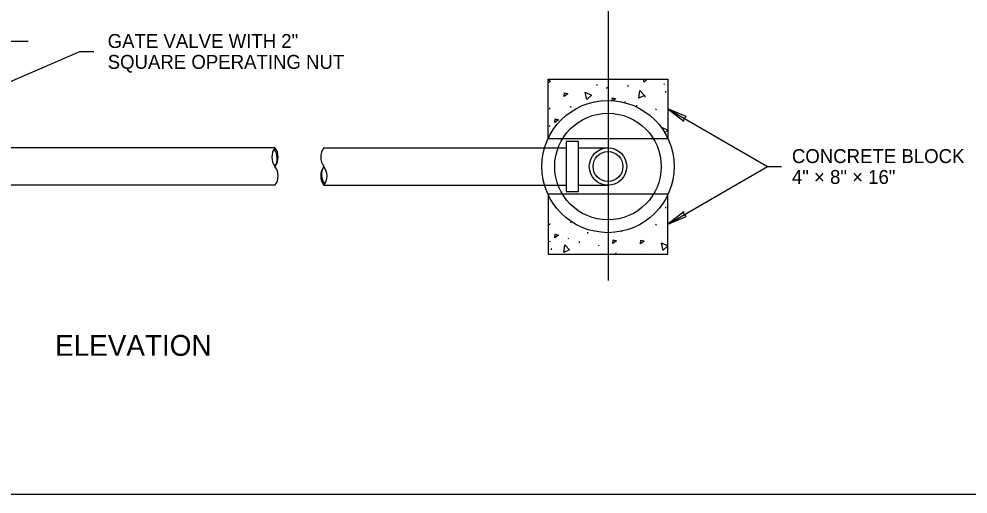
# Model space of a CAD drawing. Extents: x 99862 to 103151, y 99999 to 102075.
# Drawn here: x 100960 to 102052, y 99999 to 100546 of the extents above; entities that cross this region are included whole.
import ezdxf

# ---------------------------------------------------------------- set-up
doc = ezdxf.new("R2010")
doc.units = 0
for name, color, linetype in [('Level 1', 7, 'Continuous'), ('Level 13', 7, 'Continuous'), ('Level 15', 7, 'Continuous'), ('Level 17', 7, 'Continuous'), ('Level 19', 7, 'Continuous'), ('Level 20', 7, 'Continuous'), ('Level 6', 7, 'Continuous')]:
    doc.layers.add(name, color=color, linetype=linetype)

msp = doc.modelspace()

# ---------------------------------------------------------------- linework, layer by layer
at = {"layer": 'Level 1'}
msp.add_lwpolyline([(99862, 99999.5), (103151, 99999.5), (103151, 102075.5), (99862, 102075.5)], close=True, dxfattribs=at)
at = {"layer": 'Level 13'}
msp.add_line((100805, 100411.6), (101030.1, 100508.7), dxfattribs=at)
at = {"layer": 'Level 15'}
for p, q in [((101637.9, 101063.6), (101637.9, 100245)), ((100802.9, 100520.6), (100970.8, 100520.6)), ((101030.1, 100508.7), (101046.1, 100508.7)), ((101706.7, 100442.5), (101821.4, 100376.3)), ((101706.7, 100310), (101821.4, 100376.3)), ((101821.4, 100376.3), (101837.4, 100376.3))]:
    msp.add_line(p, q, dxfattribs=at)
for points in [[(101706.7, 100442.5), (101724.9, 100428.5), (101725.5, 100431.6), (101727.9, 100433.7)], [(101706.7, 100310), (101727.9, 100318.9), (101725.5, 100320.9), (101724.9, 100324)]]:
    msp.add_lwpolyline(points, close=True, dxfattribs=at)
at = {"layer": 'Level 17'}
for p, q in [((101706.7, 100408.1), (101568.9, 100408.1)), ((101706.7, 100344.5), (101568.9, 100344.5))]:
    msp.add_line(p, q, dxfattribs=at)
for points in [[(101568.9, 100408.1), (101568.9, 100476.9), (101706.7, 100476.9), (101706.7, 100408.1)], [(101568.9, 100344.5), (101568.9, 100275.6), (101706.7, 100275.6), (101706.7, 100344.5)]]:
    msp.add_lwpolyline(points, dxfattribs=at)
at = {"layer": 'Level 19'}
for p, q in [((101624.6, 100470.6), (101625.3, 100469.4)), ((101636.6, 100466.2), (101636.7, 100467.7)), ((101660.9, 100468.3), (101661.1, 100469.8)), ((101701.9, 100471.5), (101702.8, 100470.8)), ((101680.4, 100456.2), (101680.5, 100457.7)), ((101704.3, 100461.4), (101704.4, 100463)), ((101595.2, 100444.4), (101595.3, 100445.9)), ((101657.1, 100451), (101658, 100450.3)), ((101670.9, 100445.5), (101671, 100447)), ((101570.8, 100442.3), (101570.9, 100443.8)), ((101692.6, 100442.8), (101693.5, 100442.1)), ((101570.3, 100423.6), (101571.2, 100422.9)), ((101704.3, 100328.5), (101704.4, 100330)), ((101570.8, 100309.3), (101570.9, 100310.8)), ((101595.2, 100311.4), (101595.3, 100312.9)), ((101692.6, 100309.8), (101693.5, 100309.1)), ((101591.4, 100294), (101592.3, 100293.4)), ((101614.6, 100299.3), (101614.7, 100300.8)), ((101570.3, 100290.6), (101571.2, 100289.9)), ((101572.7, 100280.6), (101572.8, 100282.1)), ((101605.1, 100288.6), (101605.2, 100290.1)), ((101626.8, 100285.9), (101627.7, 100285.2)), ((101646.6, 100277.2), (101647.3, 100276)), ((101683, 100275.6), (101683.1, 100276.4))]:
    msp.add_line(p, q, dxfattribs=at)
for points in [[(101568.9, 100476.8), (101571.6, 100474), (101568.9, 100472.7)], [(101679.3, 100473.3), (101678.5, 100476.9)], [(101683, 100476.9), (101679.4, 100473.4)], [(101587.4, 100456.8), (101587.8, 100461.1), (101591.5, 100460), (101587.4, 100456.8)], [(101613.5, 100453.3), (101611.6, 100462), (101618.8, 100458.5), (101613.6, 100453.4)], [(101673.1, 100454.9), (101674.3, 100463.8), (101679.9, 100458.1), (101673.2, 100455)], [(101642.6, 100452.2), (101642.9, 100455.3), (101646.6, 100454.1), (101643.9, 100452.1)], [(101576.7, 100427), (101577.1, 100431.3), (101580.8, 100430.2), (101576.7, 100427)], [(101699.6, 100420.6), (101699.4, 100421.6), (101706.6, 100418.1), (101703.3, 100414.9)], [(101568.9, 100343.8), (101569.1, 100343.7)], [(101570.6, 100340.5), (101568.9, 100339.8)], [(101576.7, 100294.1), (101577.1, 100298.3), (101580.8, 100297.2), (101576.7, 100294.1)], [(101652.6, 100301.4), (101652.7, 100301.7)], [(101653.7, 100301.9), (101652.8, 100301.4)], [(101586.8, 100277.4), (101588.1, 100286.3), (101593.6, 100280.6), (101587, 100277.5)], [(101643.5, 100287.6), (101643.9, 100291.9), (101647.6, 100290.8), (101643.5, 100287.6)], [(101675.1, 100287.3), (101675.6, 100291.6), (101679.3, 100290.5), (101675.1, 100287.3)], [(101701.3, 100279.8), (101699.4, 100288.6), (101706.6, 100285.1), (101701.4, 100279.9)]]:
    msp.add_lwpolyline(points, dxfattribs=at)
at = {"layer": 'Level 6'}
for p, q in [((101254.6, 100397.8), (100832.7, 100397.8)), ((101310.9, 100397.8), (101564.9, 100397.8)), ((101564.8, 100397.8), (101589.7, 100397.8)), ((101604, 100397.8), (101637.7, 100397.8)), ((101254.6, 100354.8), (100832.7, 100354.8)), ((101310.9, 100354.8), (101564.9, 100354.8)), ((101564.8, 100354.8), (101589.7, 100354.8)), ((101604, 100354.8), (101637.7, 100354.8))]:
    msp.add_line(p, q, dxfattribs=at)
for points in [[(101604, 100347.6), (101604, 100405), (101589.7, 100405)], [(101589.7, 100405), (101589.7, 100347.6), (101604, 100347.6)]]:
    msp.add_lwpolyline(points, dxfattribs=at)
for radius in [76.1, 61.3, 21.5, 17.2]:
    msp.add_circle((101637.8, 100376.3), radius, dxfattribs=at)
for centre, radius, start, end in [((101268.5, 100387.1), 17.5, 142.1725, 217.8275), ((101240.2, 100385.5), 17.1, 327.2975, 38.8533), ((101240.8, 100387.1), 17.5, 322.1725, 37.8275), ((101324.8, 100387.1), 17.5, 142.1725, 217.8275), ((101240.8, 100365.5), 17.5, 322.1725, 37.8275), ((101324.8, 100365.5), 17.5, 142.1725, 217.8275), ((101325.2, 100366.9), 17.1, 146.7149, 218.8002), ((101297.1, 100365.5), 17.5, 322.1725, 37.8275)]:
    msp.add_arc(centre, radius, start, end, dxfattribs=at)

# ---------------------------------------------------------------- texts
at = {"layer": 'Level 20'}
for s, height, p in [('GATE VALVE WITH 2"', 16, (101062.1, 100512.7)), ('SQUARE OPERATING NUT', 16, (101062.1, 100488.7)), ('CONCRETE BLOCK', 16, (101849.4, 100380.3)), ('4" × 8" × 16"', 16, (101849.4, 100356.3)), ('ELEVATION', 24, (101001.5, 100158.5))]:
    msp.add_text(s, height=height, dxfattribs=at).set_placement(p)

doc.saveas('drawing.dxf')
